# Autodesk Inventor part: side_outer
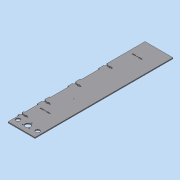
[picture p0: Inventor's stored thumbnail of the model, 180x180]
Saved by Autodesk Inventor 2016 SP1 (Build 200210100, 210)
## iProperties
Created: 2016-06
Part Number: side_outer
Material: Generic
Document SubType Name: Modeling
Designer: Mohamed A.
Density: 1 g/cm^3
Appearance: Default
d0: 1.000 ul
d0_1: 85.000 mm
d1: 320.000 mm
d2: 3.000 mm
d3: 0.00 deg
Author: Mohamed A.
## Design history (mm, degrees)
derived "side.ipt" dims count "d0" = 1
sketch "Sketch2"
  geometry: 1 further point
sketch "Sketch3"
  geometry: L1 (3, 273.4)-(0, 273.4) reference; L2 (85, 320)-(3, 320) reference; L3 (3, 273.4)-(3, 320) reference; L4 (3, 320)-(0, 320); L5 (0, 320)-(0, 278.4); L6 (0, 278.4)-(3, 278.4); L7 (3, 221.8)-(0, 221.8); L8 (0, 221.8)-(0, 185.2); L9 (0, 185.2)-(3, 185.2); L10 (0, 226.8)-(3, 226.8) reference; L11 (3, 180.2)-(0, 180.2) reference; L12 (0, 128.6)-(3, 128.6); L13 (3, 128.6)-(3, 92); L14 (3, 92)-(0, 92); L15 (0, 92)-(0, 128.6); L16 (0, 133.6)-(3, 133.6) reference; L17 (3, 221.8)-(3, 185.2); L18 (3, 226.8)-(3, 180.2) reference; L19 (3, 56)-(3, 28) reference; L20 (3, 51)-(0, 51); L21 (0, 51)-(0, 33); L22 (0, 33)-(3, 33); L23 (3, 33)-(3, 51); L24 (0, 56)-(3, 56) reference; L25 (3, 28)-(0, 28) reference; L26 (3, 87)-(0, 87) reference; 1 further point
  constraints: 30 end point, 6 perpendicular, 4 horizontal, 4 parallel, 2 collinear, 2 point on line
  dimensions: "d4" = 5 distance between parallel lines of L1 L6; "d5" = 5 distance between parallel lines of L10 L7; "d6" = 5 distance between parallel lines of L11 L9; "d7" = 5 distance between parallel lines of L16 L12; "d58" = 5 distance between parallel lines of L24 L20; "d59" = 5 distance between parallel lines of L25 L22; "d72" = 5 distance between parallel lines of L26 L14
extrude "Extrusion1" join sketch "Sketch3" distance "d9" = 3; taper "d10" = 0 deg
sketch "Sketch4"
  geometry: L1 (0, 273.4)-(3, 273.4) reference; L2 (0, 273.4)-(3, 273.4); L3 (3, 273.4)-(3, 226.8); L4 (3, 226.8)-(0, 226.8); L5 (0, 226.8)-(0, 273.4); L6 (0, 180.2)-(3, 180.2) reference; L7 (0, 180.2)-(3, 180.2); L8 (3, 180.2)-(3, 133.424); L9 (3, 133.424)-(0, 133.424); L10 (0, 133.424)-(0, 180.2); L11 (0, 248.55)-(0, 251.65); L12 (0, 28)-(0, 56) reference; L13 (0, 87)-(3, 87); L14 (3, 87)-(3, 56); L15 (3, 56)-(0, 56); L16 (0, 56)-(0, 87); L17 (0, 28)-(0, 0) reference; L18 (0, 28)-(3, 28); L19 (3, 28)-(3, 0); L20 (3, 0)-(0, 0); L21 (0, 0)-(0, 28); 1 further point
  constraints: 34 end point, 8 parallel, 4 horizontal, 4 perpendicular, 3 point on line
extrude "Extrusion2" cut sketch "Sketch4" distance "d11" = 3; taper "d12" = 0 deg
sketch "Sketch5"
  geometry: L1 (0, 300.75)-(21, 300.75); L2 (21, 300.75)-(21, 297.65); L3 (21, 297.65)-(0, 297.65); L4 (0, 297.65)-(0, 300.75); L5 (13, 302.2)-(16, 302.2); L6 (16, 302.2)-(16, 296.2); L7 (16, 296.2)-(13, 296.2); L8 (13, 296.2)-(13, 302.2); L9 (25.696, 299.2)-(-8.259, 299.2); L10 (0, 278.4)-(0, 320) reference; L11 (3, 278.4)-(0, 278.4) reference; L12 (85, 320)-(0, 320) reference; L13 (0, 303.7)-(3, 303.7); L14 (3, 303.7)-(3, 294.7); L15 (3, 294.7)-(0, 294.7); L16 (0, 294.7)-(0, 303.7); L17 (3, 221.8)-(0, 221.8) reference; L18 (21, 201.95)-(0, 201.95); L19 (0, 205.05)-(21, 205.05); L20 (21, 205.05)-(21, 201.95); L21 (16, 200.5)-(13, 200.5); L22 (13, 200.5)-(13, 206.5); L23 (0, 208)-(3, 208); L24 (3, 208)-(3, 199); L25 (16, 206.5)-(16, 200.5); L26 (13, 206.5)-(16, 206.5); L27 (3, 199)-(0, 199); L28 (25.696, 203.5)-(-8.259, 203.5); L29 (0, 199)-(0, 208); L30 (21, 108.75)-(0, 108.75); L31 (0, 111.85)-(21, 111.85); L32 (21, 111.85)-(21, 108.75); L33 (16, 107.3)-(13, 107.3); L34 (13, 107.3)-(13, 113.3); L35 (0, 114.8)-(3, 114.8); L36 (3, 114.8)-(3, 105.8); L37 (16, 113.3)-(16, 107.3); L38 (13, 113.3)-(16, 113.3); L39 (3, 105.8)-(0, 105.8); L40 (25.696, 110.3)-(-8.259, 110.3); L41 (0, 105.8)-(0, 114.8); L42 (0, 185.2)-(3, 185.2) reference; L43 (3, 92)-(0, 92) reference; L44 (0, 128.6)-(3, 128.6) reference; L45 (0, 205.05)-(0, 201.95); L46 (0, 221.8)-(0, 185.2) reference; L47 (0, 111.85)-(0, 108.75); L48 (0, 92)-(0, 128.6) reference; L49 (0, 43.55)-(21, 43.55); L50 (0, 38.25)-(0, 45.75); L51 (0, 43.55)-(0, 40.45); L52 (21, 40.45)-(0, 40.45); L53 (3, 38.25)-(0, 38.25); L54 (0, 45.75)-(3, 45.75); L55 (3, 45.75)-(3, 38.25); L56 (13, 39)-(13, 45); L57 (13, 45)-(16, 45); L58 (16, 39)-(13, 39); L59 (16, 45)-(16, 39); L60 (21, 43.55)-(21, 40.45); L61 (25.696, 42)-(-8.259, 42); L62 (0, 33)-(3, 33) reference; L63 (3, 51)-(0, 51) reference; 1 further point
  constraints: 104 end point, 21 parallel, 16 horizontal, 12 perpendicular, 3 collinear, 1 point on line, 12 other
  dimensions: "d27" = 21 distance of L2.end L3.end; "d28" = 3.1 distance of L1.end L2.end; "d29" = 3 distance of L6.end L7.end; "d30" = 6 distance of L5.end L6.end; "d31" = 41.6 distance between parallel lines of L11 L12 (derived); "d32" = 20.8 distance between parallel lines of L9 L12 (= 0.5 x d31); "d33" = 5 distance between parallel lines of L6 L2; "d34" = 9 distance between parallel lines of L15 L13; "d35" = 3 distance between parallel lines of L16 L14; "d36" = 56.6 distance between parallel lines of L17 L11 (derived); "d37" = 21 distance of L18.start L18.end; "d38" = 3.1 distance of L19.end L18.start; "d39" = 3 distance of L21.start L21.end; "d40" = 6 distance of L25.start L21.start; "d41" = 5 distance between parallel lines of L25 L20; "d42" = 9 distance between parallel lines of L27 L23; "d43" = 3 distance between parallel lines of L29 L24; "d44" = 21 distance of L30.start L30.end; "d45" = 3.1 distance of L31.end L30.start; "d46" = 3 distance of L33.start L33.end; "d47" = 6 distance of L37.start L33.start; "d48" = 5 distance between parallel lines of L37 L32; "d49" = 9 distance between parallel lines of L39 L35; "d50" = 3 distance between parallel lines of L41 L36; "d52" = 36.6 distance between parallel lines of L17 L42 (derived); "d53" = 18.3 distance between parallel lines of L28 L17 (= 0.5 x d52); "d54" = 36.6 distance between parallel lines of L43 L44 (derived); "d55" = 18.3 distance between parallel lines of L44 L40 (= 0.5 x d54); "d60" = 21 distance of L52.start L51.end; "d61" = 3.1 distance of L49.end L52.start; "d62" = 3 distance of L58.start L56.start; "d63" = 6 distance of L57.end L58.start; "d64" = 5 distance between parallel lines of L59 L60; "d65" = 7.5 distance between parallel lines of L53 L54; "d66" = 3 distance between parallel lines of L50 L55; "d67" = 18 distance between parallel lines of L62 L63 (derived); "d68" = 9 distance between parallel lines of L61 L63 (= 0.5 x d67)
extrude "Extrusion3" cut sketch "Sketch5" distance "d56" = 3; taper "d57" = 0 deg
sketch "Sketch7"
  geometry: L1 (0, 0)-(-85, 0) reference; L2 (0, 3)-(0, 0) reference; L3 (-85, 3)-(0, 3) reference; L4 (-85, 0)-(-85, 3) reference; 1 further point
extrude "Extrusion5" join sketch "Sketch7" distance "d73" = 100; taper "d74" = 0 deg
sketch "Sketch8"
  geometry: L1 (64, 43.55)-(69, 43.55) reference; L2 (69, 43.55)-(69, 45) reference; L3 (69, 45)-(72, 45) reference; L4 (72, 45)-(72, 43.55) reference; L5 (72, 43.55)-(82, 43.55) reference; L6 (82, 43.55)-(82, 45.75) reference; L7 (82, 45.75)-(85, 45.75) reference; L8 (85, 45.75)-(85, 51) reference; L9 (85, 51)-(82, 51) reference; L10 (82, 51)-(82, 92) reference; L11 (82, 92)-(85, 92) reference; L12 (85, 92)-(85, 105.8) reference; L13 (85, 105.8)-(82, 105.8) reference; L14 (82, 105.8)-(82, 108.75) reference; L15 (82, 108.75)-(72, 108.75) reference; L16 (72, 108.75)-(72, 107.3) reference; L17 (72, 107.3)-(69, 107.3) reference; L18 (69, 107.3)-(69, 108.75) reference; L19 (69, 108.75)-(64, 108.75) reference; L20 (64, 108.75)-(64, 111.85) reference; L21 (64, 111.85)-(69, 111.85) reference; L22 (69, 111.85)-(69, 113.3) reference; L23 (69, 113.3)-(72, 113.3) reference; L24 (72, 113.3)-(72, 111.85) reference; L25 (72, 111.85)-(82, 111.85) reference; L26 (82, 111.85)-(82, 114.8) reference; L27 (82, 114.8)-(85, 114.8) reference; L28 (85, 114.8)-(85, 128.6) reference; L29 (85, 128.6)-(82, 128.6) reference; L30 (82, 128.6)-(82, 185.2) reference; L31 (82, 185.2)-(85, 185.2) reference; L32 (85, 185.2)-(85, 199) reference; L33 (85, 199)-(82, 199) reference; L34 (82, 199)-(82, 201.95) reference; L35 (82, 201.95)-(72, 201.95) reference; L36 (72, 201.95)-(72, 200.5) reference; L37 (72, 200.5)-(69, 200.5) reference; L38 (69, 200.5)-(69, 201.95) reference; L39 (69, 201.95)-(64, 201.95) reference; L40 (64, 201.95)-(64, 205.05) reference; L41 (64, 205.05)-(69, 205.05) reference; L42 (69, 205.05)-(69, 206.5) reference; L43 (69, 206.5)-(72, 206.5) reference; L44 (72, 206.5)-(72, 205.05) reference; L45 (72, 205.05)-(82, 205.05) reference; L46 (82, 205.05)-(82, 208) reference; L47 (82, 208)-(85, 208) reference; L48 (85, 208)-(85, 221.8) reference; L49 (85, 221.8)-(82, 221.8) reference; L50 (82, 221.8)-(82, 278.4) reference; L51 (82, 278.4)-(85, 278.4) reference; L52 (85, 278.4)-(85, 294.7) reference; L53 (85, 294.7)-(82, 294.7) reference; L54 (82, 294.7)-(82, 297.65) reference; L55 (82, 297.65)-(72, 297.65) reference; L56 (72, 297.65)-(72, 296.2) reference; L57 (72, 296.2)-(69, 296.2) reference; L58 (69, 296.2)-(69, 297.65) reference; L59 (69, 297.65)-(64, 297.65) reference; L60 (64, 297.65)-(64, 300.75) reference; L61 (64, 300.75)-(69, 300.75) reference; L62 (69, 300.75)-(69, 302.2) reference; L63 (69, 302.2)-(72, 302.2) reference; L64 (72, 302.2)-(72, 300.75) reference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; C1 r 8.5 at (42.5, 21) reference; C2 r 6.3 at (72.2, 21) reference; C3 r 1.4 at (32.578, 15.272) reference; C4 r 1.4 at (54.505, 85.5) reference; C5 r 1.4 at (54.505, 288.5) reference; C6 r 1.4 at (42.5, 32.457) reference; C7 r 1.4 at (52.422, 15.272) reference; C8 r 6.3 at (12.8, 21) reference; 1 further point
extrude "Extrusion6" join sketch "Sketch8" distance "d75" = 3; taper "d76" = 0 deg
sketch "Sketch9"
  geometry: L1 (72.005, 367)-(72.005, 370) reference; L2 (72.005, 370)-(62.005, 370) reference; L3 (62.005, 370)-(62.005, 367) reference; L4 (62.005, 367)-(72.005, 367) reference; L5 (53.005, 367)-(53.005, 370) reference; L6 (53.005, 370)-(43.005, 370) reference; L7 (43.005, 370)-(43.005, 367) reference; L8 (43.005, 367)-(53.005, 367) reference; L9 (59.005, 84)-(69.005, 84) reference; L10 (69.005, 84)-(69.005, 87) reference; L11 (69.005, 87)-(59.005, 87) reference; L12 (59.005, 87)-(59.005, 84) reference; L13 (72, 39)-(72, 45) reference; L14 (72, 45)-(69, 45) reference; L15 (69, 45)-(69, 39) reference; L16 (69, 39)-(72, 39) reference; L17 (72, 296.2)-(72, 302.2) reference; L18 (72, 302.2)-(69, 302.2) reference; L19 (69, 302.2)-(69, 296.2) reference; L20 (69, 296.2)-(72, 296.2) reference; L21 (72, 200.5)-(72, 205.05) reference; L22 (72, 205.05)-(69, 205.05) reference; L23 (69, 205.05)-(69, 200.5) reference; L24 (69, 200.5)-(72, 200.5) reference; L25 (72, 107.3)-(72, 113.3) reference; L26 (72, 113.3)-(69, 113.3) reference; L27 (69, 113.3)-(69, 107.3) reference; L28 (69, 107.3)-(72, 107.3) reference; L29 (50.005, 87)-(40.005, 87) reference; L30 (40.005, 87)-(40.005, 84) reference; L31 (40.005, 84)-(50.005, 84) reference; L32 (50.005, 84)-(50.005, 87) reference; L33 (85, 133.6)-(82, 133.6) reference; L34 (82, 133.6)-(82, 87) reference; L35 (82, 87)-(85, 87) reference; L36 (85, 87)-(85, 56) reference; L37 (85, 56)-(82, 56) reference; L38 (82, 56)-(82, 28) reference; L39 (82, 28)-(85, 28) reference; L40 (85, 28)-(85, 0) reference; L41 (85, 0)-(0, 0) reference; L42 (0, 0)-(0, 420) reference; L43 (85, 420)-(0, 420) reference; L44 (85, 320)-(85, 420) reference; L45 (85, 320)-(82, 320) reference; L46 (82, 320)-(82, 273.4) reference; L47 (82, 273.4)-(85, 273.4) reference; L48 (85, 273.4)-(85, 226.8) reference; L49 (85, 226.8)-(82, 226.8) reference; L50 (82, 226.8)-(82, 180.2) reference; L51 (82, 180.2)-(85, 180.2) reference; L52 (85, 180.2)-(85, 133.6) reference; C1 r 1.4 at (57.505, 368.5) reference; C2 r 6.3 at (12.8, 21) reference; C3 r 1.4 at (52.422, 15.272) reference; C4 r 1.4 at (42.5, 32.457) reference; C5 r 1.4 at (54.505, 85.5) reference; C6 r 1.4 at (32.578, 15.272) reference; C7 r 6.3 at (72.2, 21) reference; C8 r 8.5 at (42.5, 21) reference; 1 further point
extrude "Extrusion7" cut sketch "Sketch9" distance "d77" = 3; taper "d78" = 0 deg
feature "Solid1::side.ipt" dims count "d0" = 1
tag "TaggingFeature1"
node "Projected Loop1"
node "Projected Loop2"
node "Reference3"
body "Solid1"
other parameters: "d0_1" = 85, "d1" = 320, "d2" = 3, "d3" = 0 deg
